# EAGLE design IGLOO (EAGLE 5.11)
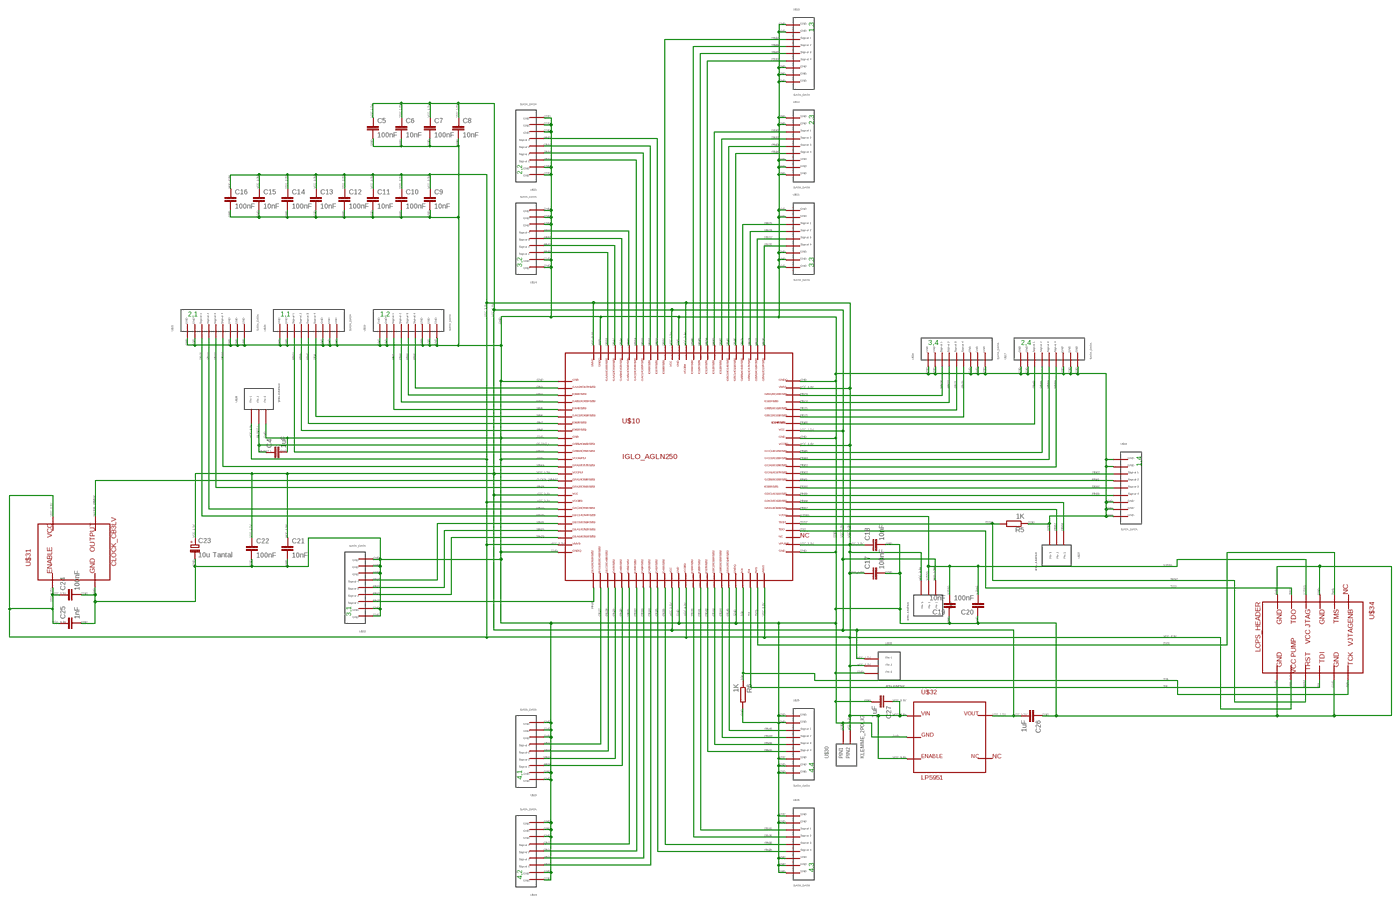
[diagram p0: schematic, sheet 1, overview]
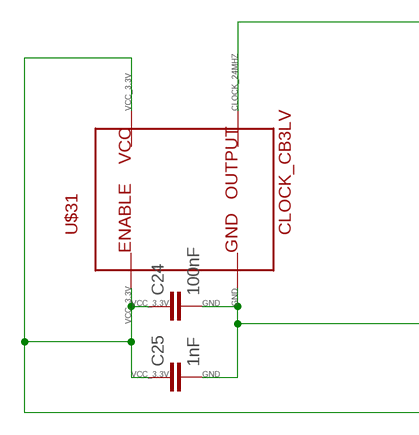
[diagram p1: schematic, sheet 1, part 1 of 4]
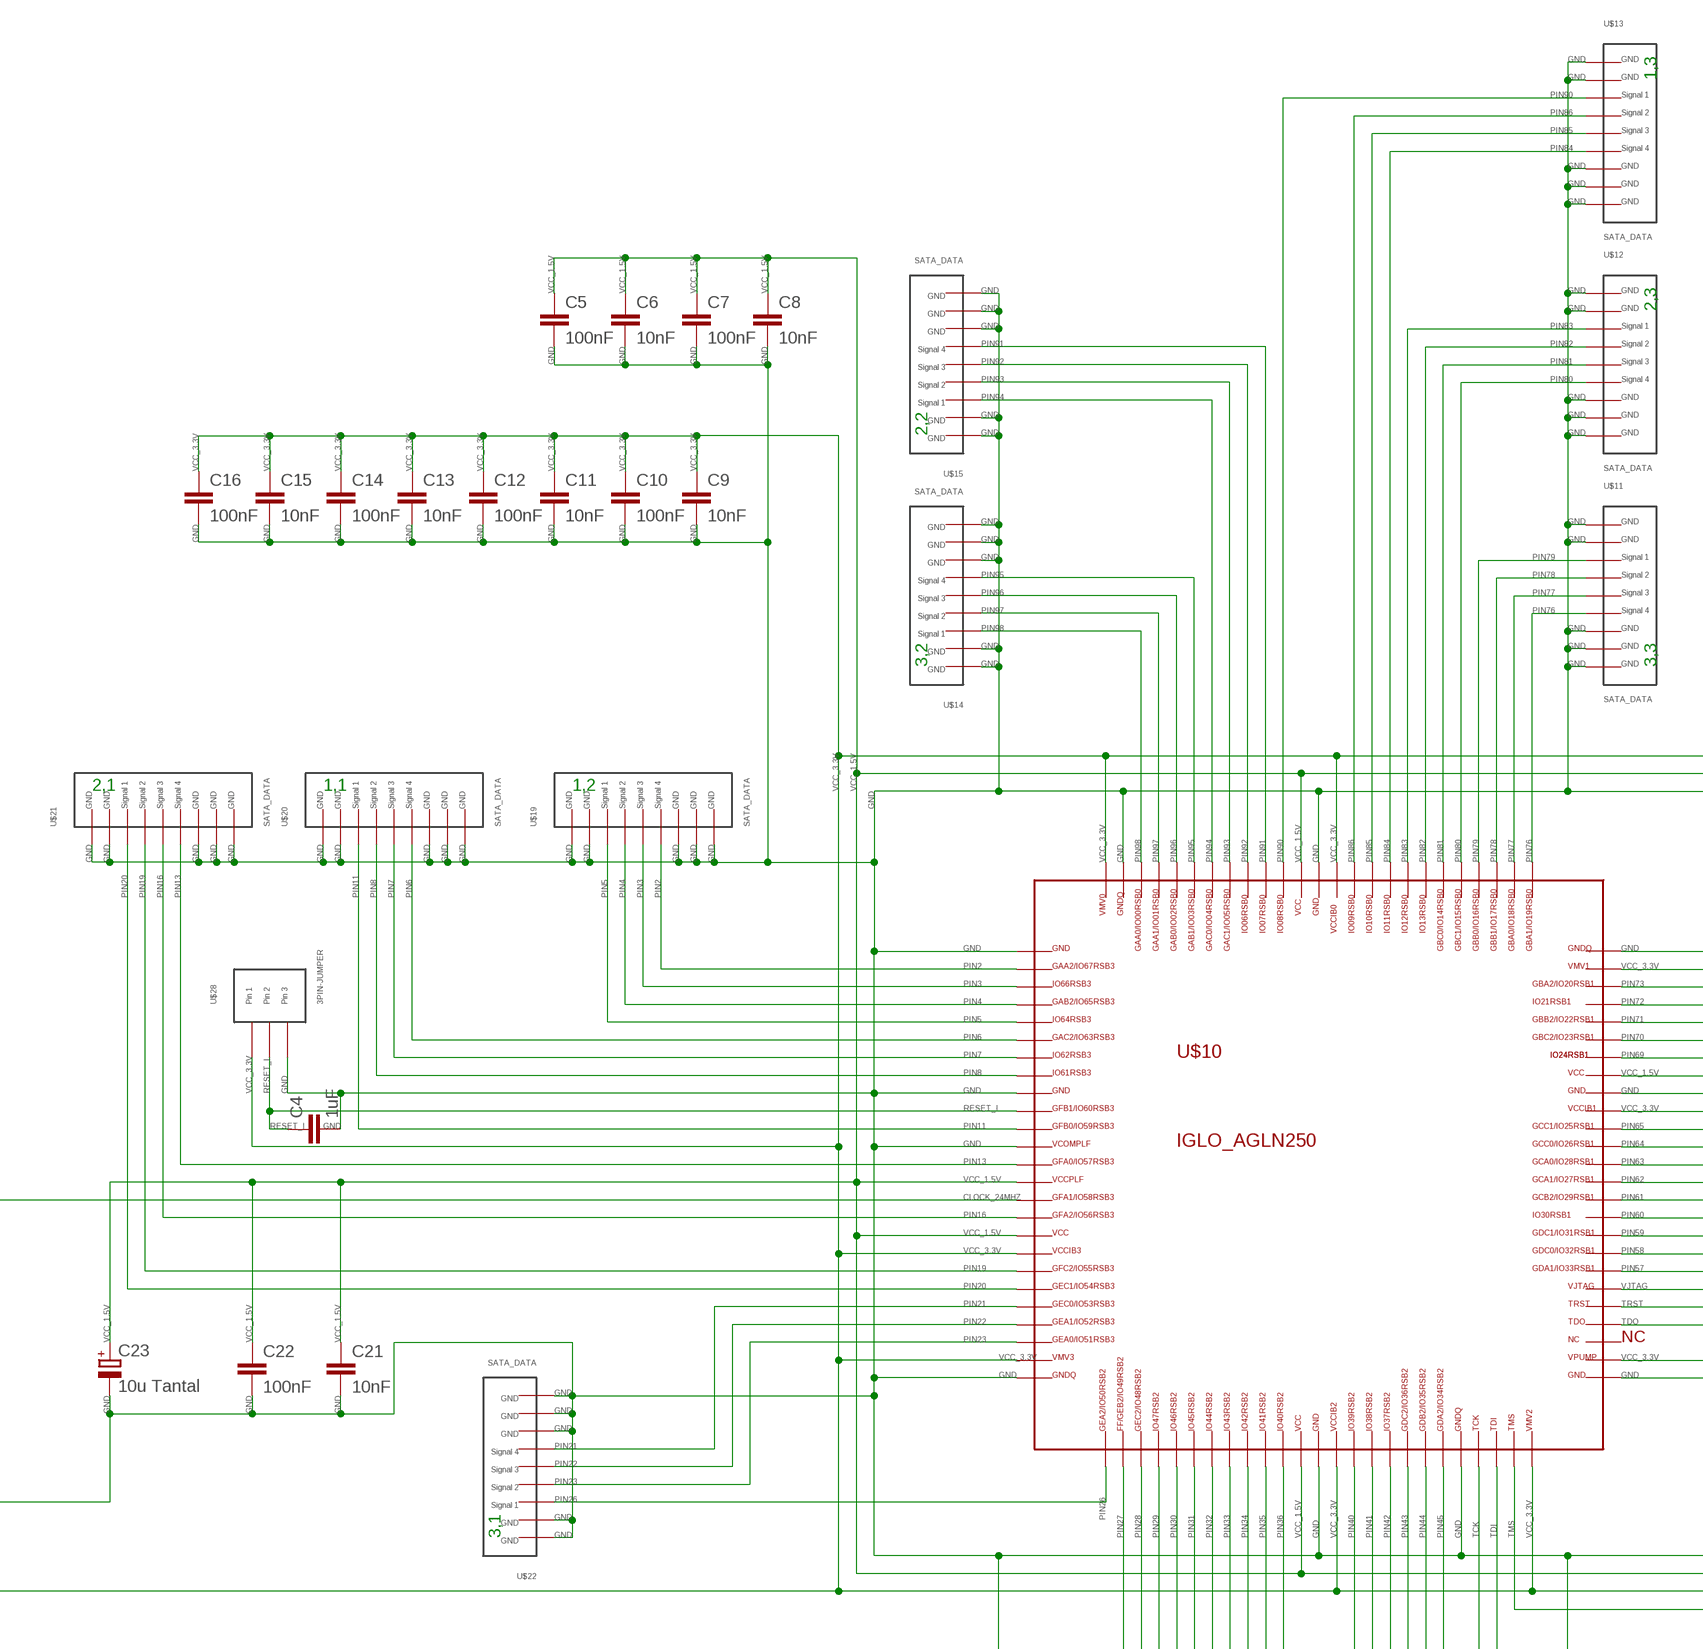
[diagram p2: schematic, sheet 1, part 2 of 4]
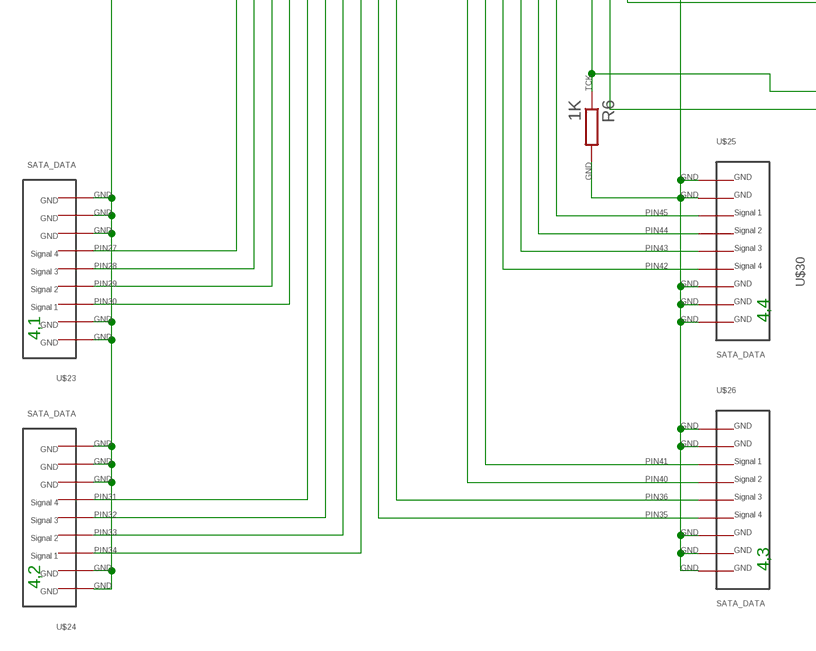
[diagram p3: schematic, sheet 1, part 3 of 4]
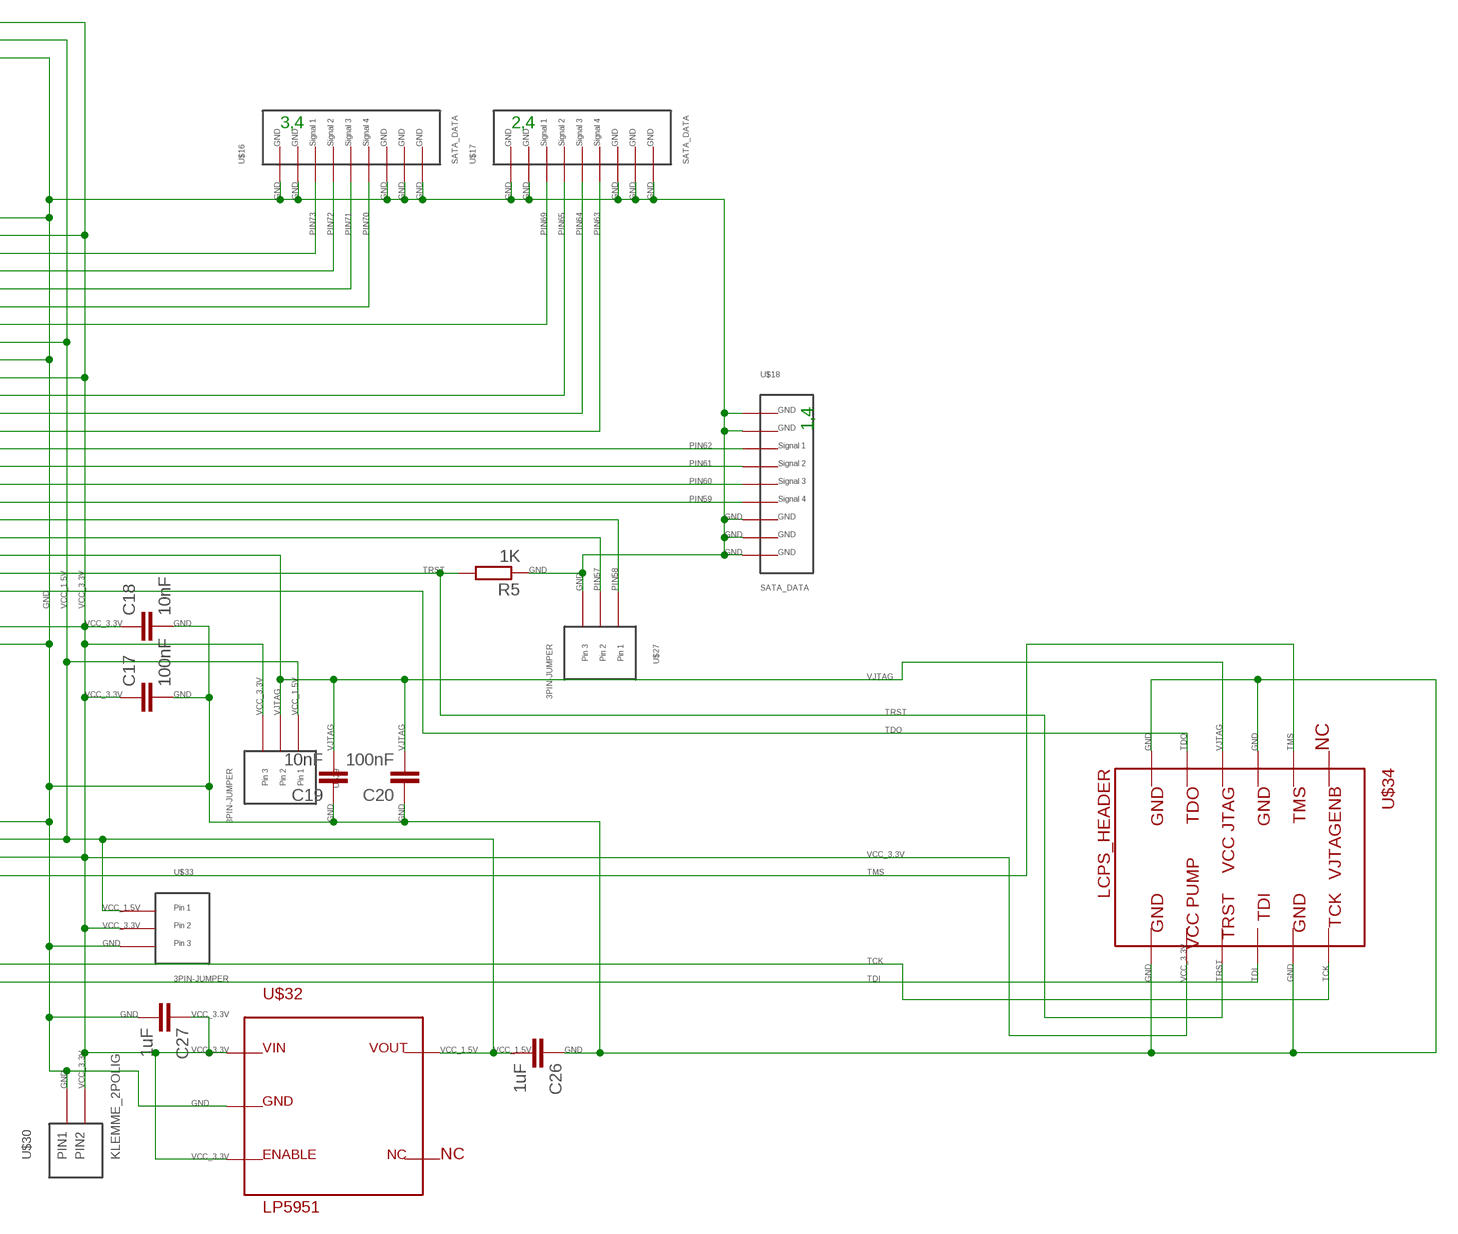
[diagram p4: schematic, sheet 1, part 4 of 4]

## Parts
C4  1uF  C-EUC0805  [C0805]
C5  100nF  C-EUC0805  [C0805]
C6  10nF  C-EUC0805  [C0805]
C7  100nF  C-EUC0805  [C0805]
C8  10nF  C-EUC0805  [C0805]
C9  10nF  C-EUC0805  [C0805]
C10  100nF  C-EUC0805  [C0805]
C11  10nF  C-EUC0805  [C0805]
C12  100nF  C-EUC0805  [C0805]
C13  10nF  C-EUC0805  [C0805]
C14  100nF  C-EUC0805  [C0805]
C15  10nF  C-EUC0805  [C0805]
C16  100nF  C-EUC0805  [C0805]
C17  100nF  C-EUC0805  [C0805]
C18  10nF  C-EUC0805  [C0805]
C19  10nF  C-EUC0805  [C0805]
C20  100nF  C-EUC0805  [C0805]
C21  10nF  C-EUC0805  [C0805]
C22  100nF  C-EUC0805  [C0805]
C23  10u Tantal  CPOL-EUSMCA  [SMC_A]
C24  100nF  C-EUC0805  [C0805]
C25  1nF  C-EUC0805  [C0805]
C26  1uF  C-EUC0805  [C0805]
C27  1uF  C-EUC0805  [C0805]
R5  1K  R-EU_R0805  [R0805]
R6  1K  R-EU_R0805  [R0805]
U$10  IGLO_AGLN250  [VQ100]
U$11  SATA_DATA  [MOLEX_SATA_PLUG]
U$12  SATA_DATA  [MOLEX_SATA_PLUG]
U$13  SATA_DATA  [MOLEX_SATA_PLUG]
U$14  SATA_DATA  [MOLEX_SATA_PLUG]
U$15  SATA_DATA  [MOLEX_SATA_PLUG]
U$16  SATA_DATA  [MOLEX_SATA_PLUG]
U$17  SATA_DATA  [MOLEX_SATA_PLUG]
U$18  SATA_DATA  [MOLEX_SATA_PLUG]
U$19  SATA_DATA  [MOLEX_SATA_PLUG]
U$20  SATA_DATA  [MOLEX_SATA_PLUG]
U$21  SATA_DATA  [MOLEX_SATA_PLUG]
U$22  SATA_DATA  [MOLEX_SATA_PLUG]
U$23  SATA_DATA  [MOLEX_SATA_PLUG]
U$24  SATA_DATA  [MOLEX_SATA_PLUG]
U$25  SATA_DATA  [MOLEX_SATA_PLUG]
U$26  SATA_DATA  [MOLEX_SATA_PLUG]
U$27  3PIN-JUMPER  [3PIN_JUMPER]
U$28  3PIN-JUMPER  [3PIN_JUMPER]
U$29  3PIN-JUMPER  [3PIN_JUMPER]
U$30  KLEMME_2POLIG  [KLEMME_2POL_PACK]
U$31  CLOCK_CB3LV  [CLOCK_CB3LV]
U$32  LP5951  [DBV]
U$33  3PIN-JUMPER  [3PIN_JUMPER]
U$34  LCPS_HEADER  [LCPS_HEADER]

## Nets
CLOCK_24MHZ: U$10.P$15 U$31.P$3
GND: C4.2 C5.2 C6.2 C7.2 C8.2 C9.2 C10.2 C11.2 C12.2 C13.2 C14.2 C15.2 C16.2 C17.2 C18.2 C19.1 C20.1 C21.2 C22.2 C23.- C24.2 C25.2 C26.1 C27.2 R5.1 R6.2 U$10.P$1 U$10.P$9 U$10.P$12 U$10.P$25 U$10.P$38 U$10.P$46 U$10.P$51 U$10.P$67 U$10.P$75 U$10.P$88 U$10.P$99 U$11.P$1 U$11.P$4 U$11.P$7 U$11.P$8 U$11.P$9 U$12.P$1 U$12.P$4 U$12.P$7 U$12.P$8 U$12.P$9 U$13.P$1 U$13.P$4 U$13.P$7 U$13.P$8 U$13.P$9 U$14.P$1 U$14.P$4 U$14.P$7 U$14.P$8 U$14.P$9 U$15.P$1 U$15.P$4 U$15.P$7 U$15.P$8 U$15.P$9 U$16.P$1 U$16.P$4 U$16.P$7 U$16.P$8 U$16.P$9 U$17.P$1 U$17.P$4 U$17.P$7 U$17.P$8 U$17.P$9 U$18.P$1 U$18.P$4 U$18.P$7 U$18.P$8 U$18.P$9 U$19.P$1 U$19.P$4 U$19.P$7 U$19.P$8 U$19.P$9 U$20.P$1 U$20.P$4 U$20.P$7 U$20.P$8 U$20.P$9 U$21.P$1 U$21.P$4 U$21.P$7 U$21.P$8 U$21.P$9 U$22.P$1 U$22.P$4 U$22.P$7 U$22.P$8 U$22.P$9 U$23.P$1 U$23.P$4 U$23.P$7 U$23.P$8 U$23.P$9 U$24.P$1 U$24.P$4 U$24.P$7 U$24.P$8 U$24.P$9 U$25.P$1 U$25.P$4 U$25.P$7 U$25.P$8 U$25.P$9 U$26.P$1 U$26.P$4 U$26.P$7 U$26.P$8 U$26.P$9 U$27.P$3 U$28.P$3 U$30.P$1 U$31.P$2 U$32.P$2 U$33.P$3 U$34.P$4 U$34.P$5 U$34.P$11 U$34.P$12
PIN2: U$10.P$2 U$19.P$6
PIN3: U$10.P$3 U$19.P$5
PIN4: U$10.P$4 U$19.P$3
PIN5: U$10.P$5 U$19.P$2
PIN6: U$10.P$6 U$20.P$6
PIN7: U$10.P$7 U$20.P$5
PIN8: U$10.P$8 U$20.P$3
PIN11: U$10.P$11 U$20.P$2
PIN13: U$10.P$13 U$21.P$6
PIN16: U$10.P$16 U$21.P$5
PIN19: U$10.P$19 U$21.P$3
PIN20: U$10.P$20 U$21.P$2
PIN21: U$10.P$21 U$22.P$6
PIN22: U$10.P$22 U$22.P$5
PIN23: U$10.P$23 U$22.P$3
PIN26: U$10.P$26 U$22.P$2
PIN27: U$10.P$27 U$23.P$6
PIN28: U$10.P$28 U$23.P$5
PIN29: U$10.P$29 U$23.P$3
PIN30: U$10.P$30 U$23.P$2
PIN31: U$10.P$31 U$24.P$6
PIN32: U$10.P$32 U$24.P$5
PIN33: U$10.P$33 U$24.P$3
PIN34: U$10.P$34 U$24.P$2
PIN35: U$10.P$35 U$26.P$6
PIN36: U$10.P$36 U$26.P$5
PIN40: U$10.P$40 U$26.P$3
PIN41: U$10.P$41 U$26.P$2
PIN42: U$10.P$42 U$25.P$6
PIN43: U$10.P$43 U$25.P$5
PIN44: U$10.P$44 U$25.P$3
PIN45: U$10.P$45 U$25.P$2
PIN57: U$10.P$57 U$27.P$2
PIN58: U$10.P$58 U$27.P$1
PIN59: U$10.P$59 U$18.P$6
PIN60: U$10.P$60 U$18.P$5
PIN61: U$10.P$61 U$18.P$3
PIN62: U$10.P$62 U$18.P$2
PIN63: U$10.P$63 U$17.P$6
PIN64: U$10.P$64 U$17.P$5
PIN65: U$10.P$65 U$17.P$3
PIN69: U$10.P$69 U$17.P$2
PIN70: U$10.P$70 U$16.P$6
PIN71: U$10.P$71 U$16.P$5
PIN72: U$10.P$72 U$16.P$3
PIN73: U$10.P$73 U$16.P$2
PIN76: U$10.P$76 U$11.P$6
PIN77: U$10.P$77 U$11.P$5
PIN78: U$10.P$78 U$11.P$3
PIN79: U$10.P$79 U$11.P$2
PIN80: U$10.P$80 U$12.P$6
PIN81: U$10.P$81 U$12.P$5
PIN82: U$10.P$82 U$12.P$3
PIN83: U$10.P$83 U$12.P$2
PIN84: U$10.P$84 U$13.P$6
PIN85: U$10.P$85 U$13.P$5
PIN86: U$10.P$86 U$13.P$3
PIN90: U$10.P$90 U$13.P$2
PIN91: U$10.P$91 U$15.P$6
PIN92: U$10.P$92 U$15.P$5
PIN93: U$10.P$93 U$15.P$3
PIN94: U$10.P$94 U$15.P$2
PIN95: U$10.P$95 U$14.P$6
PIN96: U$10.P$96 U$14.P$5
PIN97: U$10.P$97 U$14.P$3
PIN98: U$10.P$98 U$14.P$2
RESET_I: C4.1 U$10.P$10 U$28.P$2
TCK: R6.1 U$10.P$47 U$34.P$2
TDI: U$10.P$48 U$34.P$6
TDO: U$10.P$54 U$34.P$9
TMS: U$10.P$49 U$34.P$3
TRST: R5.2 U$10.P$55 U$34.P$8
VCC_1.5V: C5.1 C6.1 C7.1 C8.1 C21.1 C22.1 C23.+ C26.2 U$10.P$14 U$10.P$17 U$10.P$37 U$10.P$68 U$10.P$89 U$29.P$1 U$32.P$5 U$33.P$1
VCC_3.3V: C9.1 C10.1 C11.1 C12.1 C13.1 C14.1 C15.1 C16.1 C17.1 C18.1 C24.1 C25.1 C27.1 U$10.P$18 U$10.P$24 U$10.P$39 U$10.P$50 U$10.P$52 U$10.P$66 U$10.P$74 U$10.P$87 U$10.P$100 U$28.P$1 U$29.P$3 U$30.P$2 U$31.P$1 U$31.P$4 U$32.P$1 U$32.P$3 U$33.P$2 U$34.P$10
VJTAG: C19.2 C20.2 U$10.P$56 U$29.P$2 U$34.P$7
Unconnected: U$10.P$53 U$32.P$4 U$34.P$1

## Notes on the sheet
- 1,3
- 2,3
- 2,2
- 3,2 | 3,3
- 2,1 | 1,1 | 1,2
- 3,4 | 2,4
- 1,4
- NC
- NC
- 3,1
- NC
- 4,4
- 4,1
- 4,3
- 4,2

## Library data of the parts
C4-C22 C24-C27 = rcl:C-EU: CAPACITOR, European symbol
C23 = rcl:CPOL-EU: POLARIZED CAPACITOR, European symbol
R5 R6 = rcl:R-EU_: RESISTOR, European symbol
U$10 = IGLOO_NANO:IGLO_AGLN250
U$11-U$26 = mylibs:SATA_DATA
U$27-U$29 U$33 = mylibs:3PIN-JUMPER
U$30 = mypowerlib:KLEMME_2POLIG
U$31 = CLOCK_CB3LV:CLOCK_CB3LV
U$32 = LP5951:LP5951
U$34 = LCPS_Header:LCPS_HEADER

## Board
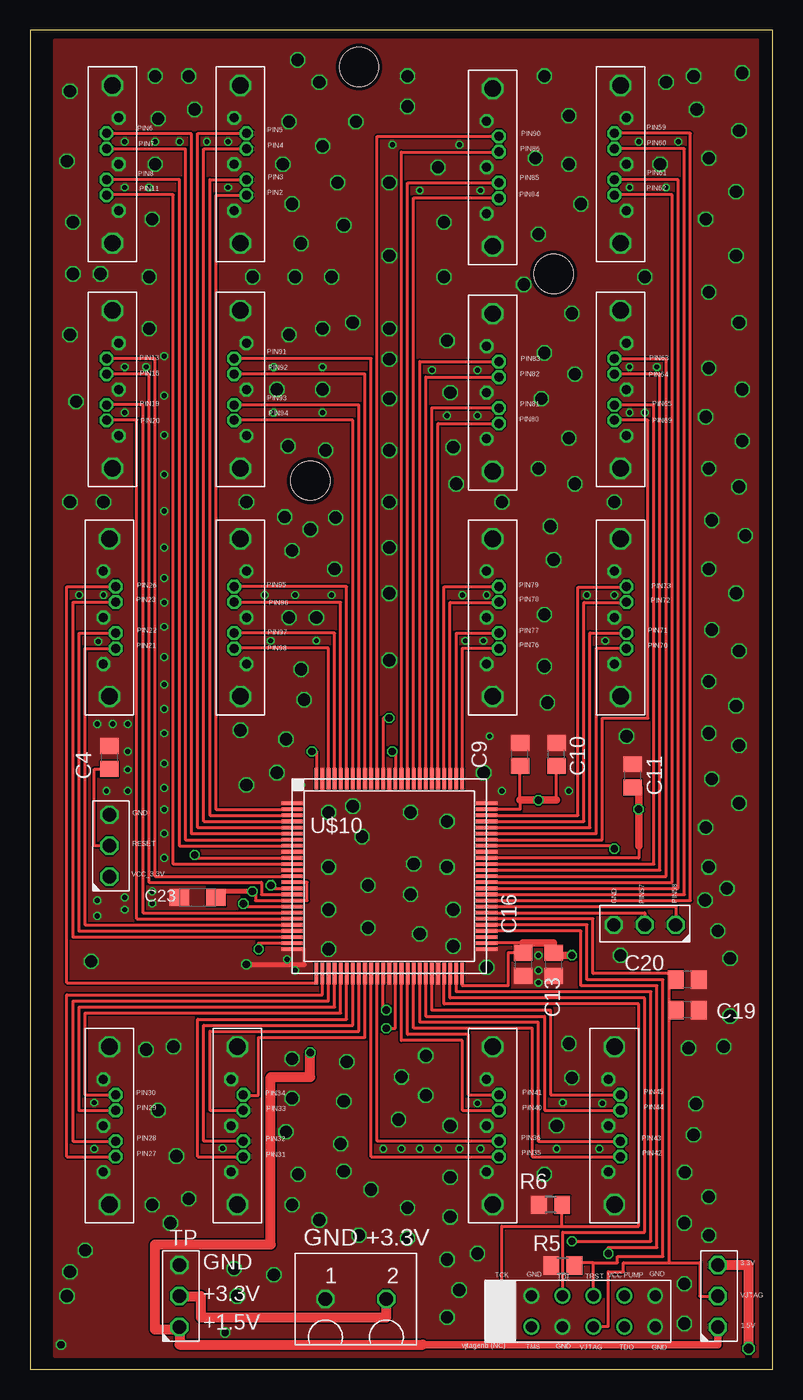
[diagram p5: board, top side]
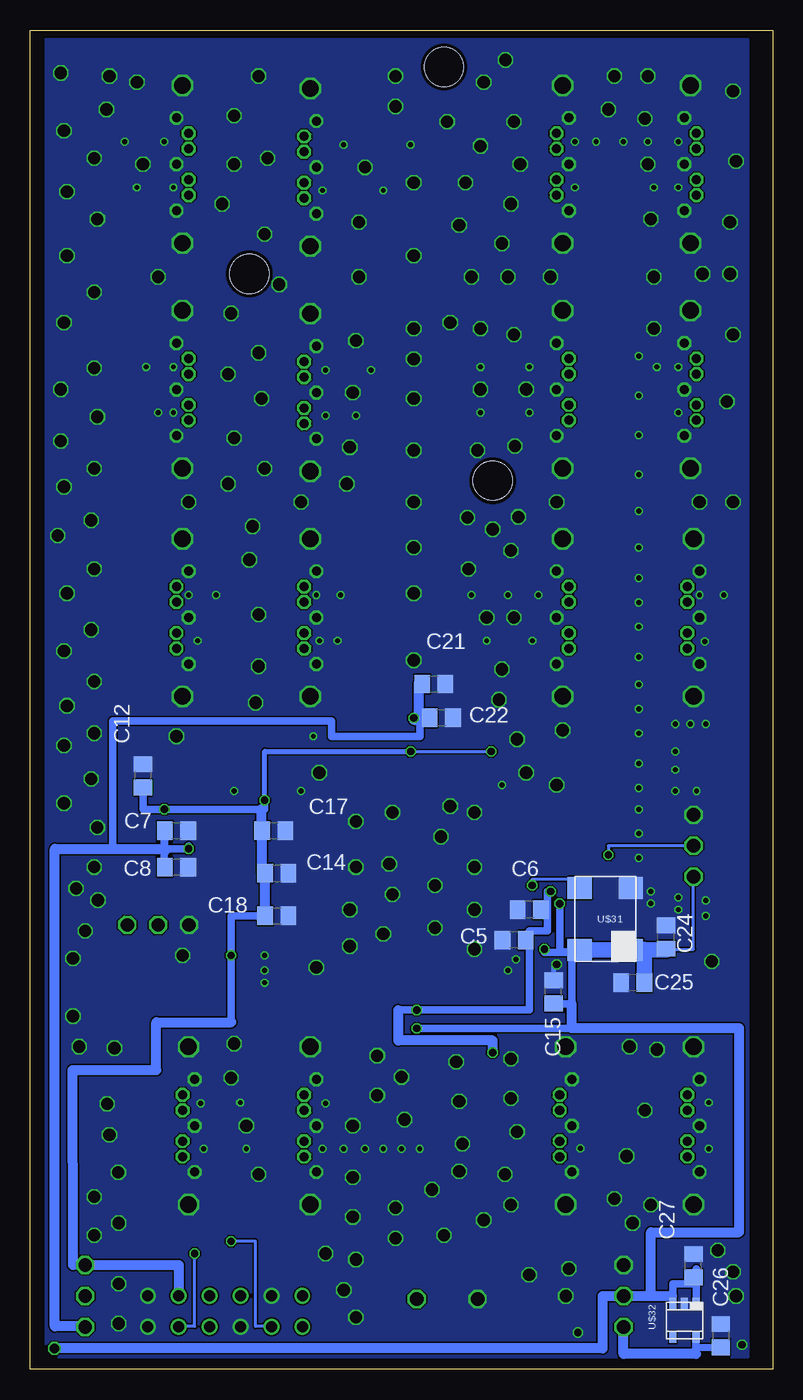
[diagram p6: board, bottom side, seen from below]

Size 61 x 110 mm. Coordinates in mm from the lower left corner, seen from the top.
Outline: 0,0 61,0 61,110 0,110 0,0
Copper layers (1*16): Top 0.035mm / dielectric 1.5mm / Bottom 0.035mm
Design rules "PCB-POOL HighSpec": minimum track width 0.125mm, minimum drill 0.2mm, track to track 0.125mm, track to pad 0.125mm, pad to pad 0.125mm, via to via 0.125mm, smd to smd 0.125mm, copper to edge 0.3mm, drill to drill 0.2mm, minimum pad ring 0.2mm, minimum via ring 0.125mm, stop-mask expansion 0.075mm, vias tented up to drill 0mil, thermal gap 0.2mm
Holes 3.2 mm at 27,107 43,90 23,73

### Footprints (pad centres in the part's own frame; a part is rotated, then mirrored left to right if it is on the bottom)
C0805 = smd 1.3 x 1.5: 1 -0.95,0; 2 0.95,0
SMC_A = smd 1.6 x 1.4: + -1.5,0; - 1.5,0
R0805 = smd 1.3 x 1.5: 1 -0.95,0; 2 0.95,0
VQ100 = smd 1.75 x 0.3: P$1 -8,6; P$2 -8,5.5; P$3 -8,5; P$4 -8,4.5; P$5 -8,4; P$6 -8,3.5; P$7 -8,3; P$8 -8,2.5; P$9 -8,2; P$10 -8,1.5; P$11 -8,1; P$12 -8,0.5; P$13 -8,0; P$14 -8,-0.5; P$15 -8,-1; P$16 -8,-1.5; P$17 -8,-2; P$18 -8,-2.5; P$19 -8,-3; P$20 -8,-3.5; P$21 -8,-4; P$22 -8,-4.5; P$23 -8,-5; P$24 -8,-5.5; P$25 -8,-6; P$51 8,-6; P$52 8,-5.5; P$53 8,-5; P$54 8,-4.5; P$55 8,-4; P$56 8,-3.5; P$57 8,-3; P$58 8,-2.5; P$59 8,-2; P$60 8,-1.5; P$61 8,-1; P$62 8,-0.5; P$63 8,0; P$64 8,0.5; P$65 8,1; P$66 8,1.5; P$67 8,2; P$68 8,2.5; P$69 8,3; P$70 8,3.5; P$71 8,4; P$72 8,4.5; P$73 8,5; P$74 8,5.5; P$75 8,6 | smd 0.3 x 1.75: P$26 -6,-8; P$27 -5.5,-8; P$28 -5,-8; P$29 -4.5,-8; P$30 -4,-8; P$31 -3.5,-8; P$32 -3,-8; P$33 -2.5,-8; P$34 -2,-8; P$35 -1.5,-8; P$36 -1,-8; P$37 -0.5,-8; P$38 0,-8; P$39 0.5,-8; P$40 1,-8; P$41 1.5,-8; P$42 2,-8; P$43 2.5,-8; P$44 3,-8; P$45 3.5,-8; P$46 4,-8; P$47 4.5,-8; P$48 5,-8; P$49 5.5,-8; P$50 6,-8; P$76 6,8; P$77 5.5,8; P$78 5,8; P$79 4.5,8; P$80 4,8; P$81 3.5,8; P$82 3,8; P$83 2.5,8; P$84 2,8; P$85 1.5,8; P$86 1,8; P$87 0.5,8; P$88 0,8; P$89 -0.5,8; P$90 -1,8; P$91 -1.5,8; P$92 -2,8; P$93 -2.5,8; P$94 -3,8; P$95 -3.5,8; P$96 -4,8; P$97 -4.5,8; P$98 -5,8; P$99 -5.5,8; P$100 -6,8
MOLEX_SATA_PLUG = drill 0.74 pad 1.016 octagon: P$1 -3.81,-0.5; P$2 -2.54,0.5; P$3 -1.27,0.5; P$4 0,-0.5; P$5 1.27,0.5; P$6 2.54,0.5; P$7 3.81,-0.5 | drill 1.35 octagon: P$8 -6.48,0; P$9 6.48,0
3PIN_JUMPER = drill 1.1 octagon: P$1 -2.54,0; P$2 0,0; P$3 2.54,0
KLEMME_2POL_PACK = drill 1.1 octagon: P$1 -2.5,0; P$2 2.5,0
CLOCK_CB3LV = smd 1.8 x 2: P$1 -2.54,-2.1; P$2 2.54,-2.1; P$3 2.54,2.1; P$4 -2.54,2.1
DBV = smd 0.6 x 0.9: P$1 -0.95,-1.4; P$2 0,-1.4; P$3 0.95,-1.4; P$4 0.95,1.4; P$5 -0.95,1.4
LCPS_HEADER = drill 0.9 round: P$1 -6.35,-1.27; P$2 -6.35,1.27; P$3 -3.81,-1.27; P$4 -3.81,1.27; P$5 -1.27,-1.27; P$6 -1.27,1.27; P$7 1.27,-1.27; P$8 1.27,1.27; P$9 3.81,-1.27; P$10 3.81,1.27; P$11 6.35,-1.27; P$12 6.35,1.27

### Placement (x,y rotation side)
C4  6.5,50.25 90 top
C5  21.25,35.25 180 bottom
C6  20,37.75 180 bottom
C7  49,44.25 0 bottom
C8  49,41.25 0 bottom
C9  40.25,50.5 90 top
C10  43.25,50.5 90 top
C11  49.5,48.75 90 top
C12  51.75,48.75 90 bottom
C13  43,33.25 270 top
C14  40.75,40.75 0 bottom
C15  18,31 90 bottom
C16  40.5,33.25 270 top
C17  41,44.25 0 bottom
C18  40.75,37.25 0 bottom
C19  54,29.5 180 top
C20  54,32 180 top
C21  27.85,56.3 0 bottom
C22  27.23,53.53 0 bottom
C23  13.75,38.75 180 top
C24  8.75,35.5 90 bottom
C25  11.5,31.75 180 bottom
C26  4.25,2.75 270 bottom
C27  6.5,8.5 90 bottom
R5  43.75,8.5 0 top
R6  42.75,13.5 180 top
U$10  29.5,40.5 0 top
U$11  38,61.75 270 top
U$12  38,80.25 270 top
U$13  38,98.75 270 top
U$14  17.25,61.75 90 top
U$15  17.25,80.5 90 top
U$16  48.5,61.75 270 top
U$17  48.5,80.5 90 top
U$18  48.5,99 90 top
U$19  17.25,99 270 top
U$20  6.75,99 90 top
U$21  6.75,80.5 90 top
U$22  6.5,61.75 270 top
U$23  6.5,20 270 top
U$24  17,20 270 top
U$25  48,20 270 top
U$26  38,20 270 top
U$27  50.5,36.5 180 top
U$28  6.5,43 90 top
U$29  56.5,6 90 top
U$30  26.75,5.75 0 top
U$31  13.75,37 90 bottom
U$32  7.25,4 180 bottom
U$33  12.25,6 90 top
U$34  45,4.75 0 top

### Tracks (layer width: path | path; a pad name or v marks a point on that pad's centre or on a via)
CLOCK_24MHZ  (via drill 0.6)
  Top 0.25: U$10.P$15 19.75,39.5 v19.75,39.75
  Bottom 0.25: v19.75,39.75 19.75,40.25 16.25,40.25 16.35,39.75 U$31.P$3
GND  (via drill 0.4, 0.6, 1)
  Top 0.25: 22.5,33.25 22.5,34.5 U$10.P$25
  Top 0.406: v17.75,33.25 22.5,33.25
  Bottom 0.406: C15.2 18,33.25 v17.75,33.25
  other vias: 24.5,45.75 27.25,43.75 24.5,41.25 27.75,39.75 24.5,37.75 27.75,36.25 24.5,34.5 31.25,45.75 34.25,45 31.5,41.5 34.25,41.25 31.25,39 34.75,37.75 32,35.75 34.75,34.75 26.5,46.25 17.75,48 17.25,52.5 22.25,57.5 21,51.75 22.5,55 20.25,49 24.25,75.5 21.18,75.85 17.75,71.25 20.9,70.03 25.07,69.97 21.5,67.25 25,65.75 23,69 6,71.25 9.75,89.75 10,94.5 9.75,85.5 18.25,89.75 21.25,85 22.25,92.5 21.75,89.75 24,85.5 24.75,89.75 26.5,86 25.75,94 21.5,95.75 25.25,97.5 20.75,99 24,100.5 21.25,102.5 23.75,105.75 26.75,102.5 31,106.25 33.5,98.75 31,103.75 21.95,107.57 10.25,106.25 10.5,102.75 13,106.25 13.5,103.5 10.25,99 3.25,105 3,99.25 3.5,94.25 3.5,90 5.75,90 42.25,106.25 44.25,103 41.5,99.5 45.25,95.75 41.75,93.25 44.25,99 34,94.25 34,89.75 40.55,89.12 50.5,89.75 52.25,105.75 51.75,99 20.25,80.5 24,80.5 29.5,83 34.5,80.25 34.75,75.75 35,72.75 42.25,83.5 44.5,86.75 44.25,76.5 44.75,81.75 42,79.75 41.75,74 44.75,72.75 34.25,84.5 29.5,97.5 29.5,91.5 29.5,85.5 29.5,79.75 29.5,75.5 29.5,71.25 29.5,67.5 29.5,63.75 29.5,58.25 23.5,61.75 21.25,61.75 3.25,85 3.75,79.5 3.25,71.25 42.75,69.25 38.75,71.25 48,71.25 43,66.5 42.25,62 42.25,57.75 42.5,54.75 9.5,26.25 11.75,26.5 10.5,21.25 12,17.5 10,13.5 13,14 25.5,18.5 22,16 28,14.75 23.75,12.25 27,11 16,3 17,6 20,7.75 16.75,8.25 11.5,12 3,6 4.5,9.75 34.5,15.75 31,13.25 25.75,16.25 31,10.75 34.5,12.5 34.25,9 34.25,4.25 36.75,9.5 35.25,6.5 53.75,7 53.75,3.75 53.75,12 44.5,23.92 55.75,11 53.77,16.17 43.25,20 30.5,24 25.75,22 54.5,19.25 55.75,14.15 54.1,26.38 54.7,21.8 57,26.5 57.5,29 57.5,33.75 48.5,34 56.5,36 57.25,39.5 55.75,41.25 55.45,38.53 55.5,44.5 58.25,46.5 56,48.5 58.25,51.25 55.75,52.25 49,52 58,54.5 55.75,56.5 58.25,59 56,60.75 58,63.75 55.75,65.75 58.75,68.5 56,69.75 58.25,72.5 55.75,74 58.5,76.25 55.5,78.25 58.5,80.5 55.75,82.25 58.25,86 55.75,88.5 58,91.5 55.5,94.5 58,96.75 55.75,99.5 58.25,101.75 54.75,103.5 58.5,106.5 54.5,106.25 21.5,25.5 26,25.25 21.5,22.25 30.25,20.5 21,19.5 42.25,16 44.25,26.75 5,33.5 21.5,13.5 37.5,33 41.75,31.75 41.75,32.75 41.75,34 10,38.25 11,42 11,44 11,46 11,47.75 11,49.75 11,52.25 5.5,53 6.75,53 8,53 8,50.75 8,49.25 8,47.5 6.25,47.5 11,54.25 11,56.25 11,58.5 11,61 11,63 11,65 11,67.5 11,70.5 11,73.5 11,76.75 11,80 11,83.25 10,39.25 37.25,49 37.75,52 38.75,47.5 44.25,47.5 21.75,32.75 22.25,48 5.5,38.5 5.5,37.25 7.75,38.75 7.75,37.75 32.5,25.75 34.5,20 3.25,8 2.5,2 5.25,21.9 5.25,18.1 15.8,18.12 30.5,18.1 43.75,21.9 43.25,18.1 32,18.1 33.5,18.1 35.25,18.1 29,18.1 37,18.1 32.5,22.5 36.75,21.85 46.75,18.1 47,21.85 6,63.6 4,63.6 23.5,59.85 19.75,59.85 19.25,63.6 24.75,63.6 21.75,63.6 35.75,59.85 37.25,59.85 37.5,63.6 35.5,63.6 47.25,59.85 48,63.6 45.75,63.6 49.25,82.35 51.5,82.35 49.25,78.6 50.5,78.6 53.25,100.85 50,100.85 49.25,97.1 52.25,97.1 35.25,100.6 29.75,100.6 32,96.85 37,96.85 20,82.35 24,82.35 20,78.6 24,78.6 33,82.1 36.75,82.1 34.25,78.35 36.75,78.35 7.75,82.35 9.5,82.35 7.75,78.6 7.75,100.85 10.25,100.85 12.25,100.85 7.75,97.1 9.75,97.1 14.5,100.85 16.25,100.85 16.25,97.1 5.57,59.8 21.1,33.67
  pour Bottom (no thermals): 2,109.25 59.75,109.25 59.75,1 2,1
  pour Top (no thermals): 2,109.25 59.75,109.25 59.75,1 2,1
PIN2
  Top 0.25: U$10.P$2 15.25,46 15.25,96.46 U$19.P$6
PIN3
  Top 0.25: U$10.P$3 14.75,45.5 14.75,97.75 17.75,97.75 U$19.P$5
PIN4
  Top 0.25: U$10.P$4 14.25,45 14.25,100.27 U$19.P$3
PIN5
  Top 0.25: U$10.P$5 13.75,44.5 13.75,101.54 U$19.P$2
PIN6
  Top 0.25: U$10.P$6 13.25,44 13.25,101.5 6.25,101.5 U$20.P$6
PIN7
  Top 0.25: U$10.P$7 12.75,43.5 12.75,100.25 6.25,100.25 U$20.P$5
PIN8
  Top 0.25: U$10.P$8 12.25,43 12.25,97.75 6.25,97.75 U$20.P$3
PIN11
  Top 0.25: U$10.P$11 11.75,41.5 11.75,96.5 6.25,96.5 U$20.P$2
PIN13
  Top 0.25: U$10.P$13 10.25,40.5 10.25,83.04 U$21.P$6
PIN16
  Top 0.25: U$10.P$16 19,39 19,40 9.75,40 9.75,81.75 6.25,81.75 U$21.P$5
PIN19
  Top 0.25: U$10.P$19 9.25,37.5 9.25,79.25 6.25,79.25 U$21.P$3
PIN20
  Top 0.25: U$10.P$20 8.75,37 8.75,78 6.25,78 U$21.P$2
PIN21
  Top 0.25: U$10.P$21 4.5,36.5 4.5,59.21 U$22.P$6
PIN22
  Top 0.25: U$10.P$22 4,36 4,60.47 U$22.P$5
PIN23
  Top 0.25: U$10.P$23 3.5,35.5 3.5,63.02 U$22.P$3
PIN26
  Top 0.25: U$10.P$26 23.5,31.75 3,31.75 3,64.29 U$22.P$2
PIN27
  Top 0.25: U$10.P$27 24,30.75 3,30.75 3,17.46 U$23.P$6
PIN28
  Top 0.25: U$10.P$28 24.5,30.25 3.5,30.25 3.5,18.73 U$23.P$5
PIN29
  Top 0.25: U$10.P$29 25,29.75 4,29.75 4,21.25 7,21.25 U$23.P$3
PIN30
  Top 0.25: U$10.P$30 25.5,29.25 4.5,29.25 4.5,22.54 U$23.P$2
PIN31
  Top 0.25: U$10.P$31 26,28.75 13.75,28.75 13.75,17.46 U$24.P$6
PIN32
  Top 0.25: U$10.P$32 26.5,28.25 14.25,28.25 14.25,18.75 17.5,18.75 U$24.P$5
PIN33
  Top 0.25: U$10.P$33 27,27.75 14.75,27.75 14.75,21.27 U$24.P$3
PIN34
  Top 0.25: U$10.P$34 27.5,27.25 18.75,27.25 18.75,22.5 17.5,22.5 U$24.P$2
PIN35
  Top 0.25: U$10.P$35 28,17.46 U$26.P$6
PIN36
  Top 0.25: U$10.P$36 28.5,18.75 38.5,18.75 U$26.P$5
PIN40
  Top 0.25: U$10.P$40 30.5,27 35.5,27 35.5,21.27 U$26.P$3
PIN41
  Top 0.25: U$10.P$41 31,27.5 36,27.5 36,22.54 U$26.P$2
PIN42
  Top 0.25: U$10.P$42 31.5,28 41.25,28 41.25,17.46 U$25.P$6
PIN43
  Top 0.25: U$10.P$43 32,28.5 41.75,28.5 41.75,18.73 U$25.P$5
PIN44
  Top 0.25: U$10.P$44 32.5,29 42.25,29 42.25,21.27 U$25.P$3
PIN45
  Top 0.25: U$10.P$45 33,29.5 42.75,29.5 42.75,22.54 U$25.P$2
PIN57
  Top 0.25: U$10.P$57 50.5,37.5 U$27.P$2
PIN58
  Top 0.25: U$10.P$58 53.04,38 U$27.P$1
PIN59
  Top 0.25: U$10.P$59 54.25,38.5 54.25,101.54 U$18.P$6
PIN60
  Top 0.25: U$10.P$60 53.75,39 53.75,100.27 U$18.P$5
PIN61
  Top 0.25: U$10.P$61 53.25,39.5 53.25,97.73 U$18.P$3
PIN62
  Top 0.25: U$10.P$62 52.75,40 52.75,96.5 48,96.5 U$18.P$2
PIN63
  Top 0.25: U$10.P$63 52.25,40.5 52.25,83 48,83 U$17.P$6
PIN64
  Top 0.25: U$10.P$64 51.75,41 51.75,81.75 48,81.75 U$17.P$5
PIN65
  Top 0.25: U$10.P$65 51.25,41.5 51.25,79.23 U$17.P$3
PIN69
  Top 0.25: U$17.P$2 50.75,77.96 50.75,53.5 47,53.5 47,43.5 U$10.P$69
PIN70
  Top 0.25: U$10.P$70 46.5,44 46.5,59.25 49,59.25 U$16.P$6
PIN71
  Top 0.25: U$10.P$71 46,44.5 46,60.5 49,60.5 U$16.P$5
PIN72
  Top 0.25: U$10.P$72 45.5,45 45.5,63 49,63 U$16.P$3
PIN73
  Top 0.25: U$10.P$73 45,45.5 45,64.25 49,64.25 | 49,64.25 49.25,64.25 | 49,64.25 U$16.P$2
PIN76
  Top 0.25: U$10.P$76 35.5,59.25 38.5,59.25 U$11.P$6
PIN77
  Top 0.25: U$10.P$77 35,60.48 U$11.P$5
PIN78
  Top 0.25: U$10.P$78 34.5,63 38.5,63 U$11.P$3
PIN79
  Top 0.25: U$10.P$79 34,64.29 U$11.P$2
PIN80
  Top 0.25: U$10.P$80 33.5,77.71 U$12.P$6
PIN81
  Top 0.25: U$10.P$81 33,79 38.5,79 U$12.P$5
PIN82
  Top 0.25: U$10.P$82 32.5,81.52 U$12.P$3
PIN83
  Top 0.25: U$10.P$83 32,82.79 U$12.P$2
PIN84
  Top 0.25: U$10.P$84 31.5,96.25 38.5,96.25 U$13.P$6
PIN85
  Top 0.25: U$10.P$85 31,97.48 U$13.P$5
PIN86
  Top 0.25: U$10.P$86 30.5,100 38.5,100 U$13.P$3
PIN90
  Top 0.25: U$10.P$90 28.5,101.29 U$13.P$2
PIN91
  Top 0.25: U$10.P$91 28,83.04 U$15.P$6
PIN92
  Top 0.25: U$10.P$92 27.5,81.77 U$15.P$5
PIN93
  Top 0.25: U$10.P$93 27,79.23 U$15.P$3
PIN94
  Top 0.25: U$10.P$94 26.5,77.96 U$15.P$2
PIN95
  Top 0.25: U$10.P$95 26,64.29 U$14.P$6
PIN96
  Top 0.25: U$10.P$96 25.5,63 16.75,63 U$14.P$5
PIN97
  Top 0.25: U$10.P$97 25,60.48 U$14.P$3
PIN98
  Top 0.25: U$10.P$98 24.5,59.25 16.75,59.25 U$14.P$2
RESET_I  (via drill 0.6)
  Top 0.25: C4.1 5.25,49.3 5.25,43 U$28.P$2 | U$10.P$10 13.5,42 v13.5,42.25
  Bottom 0.25: v13.5,42.25 13.5,43 U$28.P$2
TCK
  Top 0.25: U$10.P$47 34,30 50,30 50,11.75 43.7,11.75 | 43.7,11.75 38.75,11.75 38.75,6 38.65,6 U$34.P$2 | 43.7,11.75 R6.1
TDI
  Top 0.25: U$10.P$48 34.5,30.5 50.5,30.5 50.5,11.25 43.75,11.25 43.75,6 43.73,6 U$34.P$6
TDO  (via drill 0.6)
  Top 0.25: U$10.P$54 45.25,36 45.25,31.5 51.5,31.5 51.5,10 47.5,10 v47.5,9.5
  Bottom 0.25: v47.5,9.5 47.5,3.5 48.81,3.5 U$34.P$9
TMS  (via drill 0.6)
  Top 0.25: U$10.P$49 35,31 51,31 51,10.5 v44.5,10.5
  Bottom 0.25: v44.5,10.5 42.5,10.5 42.5,3.5 41.19,3.5 U$34.P$3
TRST
  Top 0.25: U$10.P$55 45.75,36.5 45.75,32 52,32 52,9.25 48.25,9.25 48.25,8.75 46.27,8.75 | U$34.P$8 46.27,8.75 | R5.2 44.7,8.75 46.27,8.75
VCC_1.5V  (via drill 0.6)
  Top 0.25: U$10.P$14 22.75,40 22.75,38.5 U$10.P$17 18.5,38.5 18.5,39.25 v18.25,39.25 | v29.25,29.5 29,29.5 U$10.P$37 | U$10.P$68 48,43 v48,42.75 | U$10.P$89 29,53.5 v29.5,53.5
  Top 0.406: v18.25,39.25 15.25,39.25 C23.+
  Top 0.61: U$29.P$1 56.5,2 32.25,2
  Top 0.813: U$33.P$1 12.25,3.25 | 12.25,3.25 12.25,2 32.25,2 | v23,26 23,24 19.75,24 19.75,10.25 10.25,10.25 10.25,3.25 12.25,3.25
  Bottom 0.25: 28.23,53.5 C22.1 | 29,53.5 v29.5,53.5
  Bottom 0.61: v18.25,39.25 18.5,39.25 18.5,37.75 | 18.5,37.75 18.5,36 20,36 20,35.25 | 20,35.25 20,29.5 v29.25,29.5 30.75,29.5 | 18.5,37.75 C6.1 | 20,35.25 C5.1 | 6.3,1.75 6.3,1.25 | C26.2 6.3,1.75 | 6.3,1.75 U$32.P$5 | C8.1 50,41.25 50,42.5 50,44.25 C7.1 49.95,42.75 v48,42.75 48,43 | v29.5,53.5 28.23,53.5 | 29,53.5 29,52 36.25,52 36.25,53.25 54.25,53.25 54.25,42.75
  Bottom 0.813: 6.3,1.25 12.25,1.25 U$33.P$1 12.25,3.5 | 30.75,29.5 30.75,27 23,27 v23,26 | U$29.P$1 56.5,3.5 59,3.5 59,42.75 54.25,42.75 50,42.75 50,42.5 | C21.1 29.08,56.35 29.08,53.35 29.48,53.35 29.48,53.5 v29.5,53.5
VCC_3.3V  (via drill 0.6, 0.6 pad 0.61, 0.8)
  Top 0.25: U$10.P$18 17.5,38 v17.5,38.25 | U$10.P$24 18.75,35 v18.75,34.5 | U$10.P$39 30,28 v29.25,28 | U$10.P$74 40.25,46 40.25,46.75 C9.1 | 43.25,46.75 C10.1 | U$10.P$66 50,42 50,43 | U$10.P$52 40.5,35 C16.1 39.25,34.2 39.25,31.5 35.5,31.5 U$10.P$50 | C13.1 43,35 | U$10.P$87 30,50.75 v29.75,50.75 | U$10.P$100 23.5,50.75 v23.12,50.75
  Top 0.61: 50,43 v50,46 50,47.8 C11.1 | 43.25,46.75 v41.75,46.75 40.25,46.75 | 43,35 40.5,35 | v44.5,34 43.05,34 43,34
  Top 0.813: U$33.P$2 14,6 14,4.25 29.25,4.25 U$30.P$2 | U$29.P$3 59.03,8.54 v59.03,1.7 | C13.1 43.05,34.2 43.05,34
  Bottom 0.25: 16.5,34.46 16.25,34.46 | 16.5,34.46 17.5,34.46 | 16.5,34.25 16.5,34.46 | U$28.P$1 6.5,34.5 8.75,34.5 | v29.75,50.75 v23.12,50.75 | 12,34.5 12,34.42 11.73,34.42 11.73,34.46 11.88,34.46
  Bottom 0.406: 8.2,5.5 U$32.P$3 8.2,6 8.25,6 | v29.75,50.75 41.75,50.75 v41.75,46.75
  Bottom 0.61: 17.5,34.46 v17.5,38.25 | v18.75,34.5 18.75,34.25 16.5,34.25 16.5,30 18,30 C15.1 | 16.5,28 v29.25,28 | U$32.P$1 6.25,5.4 | 6.25,7 6.25,8.25 C27.1 | C12.1 51.75,46 v50,46 42,46 41.75,46 v41.75,46.75 | 44.5,28.5 v44.5,34 44.5,37.25 C18.1 | U$32.P$3 8.2,7 6.25,7 | 6.25,5.4 6.25,7 | 6.25,5.4 6.25,5.25
  Bottom 0.813: C18.1 C14.1 41.95,40.75 C17.1 42,44.25 42,46 | 10,6 10,11.25 2.75,11.25 2.75,28 16.5,28 16.5,30 | 10,6 U$33.P$2 13.98,6 13.98,1.7 v59.03,1.7 | 8.25,6 10,6 | U$34.P$10 48.81,8.55 56.52,8.55 | 56.52,8.55 56.52,8.48 56.5,8.48 U$29.P$3 | 44.5,28.5 50.65,28.5 50.65,24.58 57.52,24.58 57.5,9.25 57.5,8.55 56.52,8.55
  Bottom 1.27: 16.25,34.46 U$31.P$4 11.88,34.46 U$31.P$1 8.75,34.46 8.75,34.5 C24.1 | C25.1 10.55,34.5 12,34.5
VJTAG
  Top 0.25: U$10.P$56 46.25,37 46.25,32.5 52.5,32.5 | 52.5,8.75 52.5,29.5 | 52.5,29.5 52.5,32.5 | 52.5,8.75 48.75,8.75 48.75,8 47.5,8 47.5,3.5 46.27,3.5 U$34.P$7 | 52.5,8.75 55,8.75 55,6 U$29.P$2 | C20.2 53.05,32.5 52.5,32.5 | 52.5,29.5 C19.2

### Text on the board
tPlace: PIN6 | PIN5 | PIN59 | PIN90 | PIN60 | PIN7 | PIN4 | PIN86 | PIN8 | PIN3 | PIN85 | PIN61 | PIN11 | PIN62 | PIN2 | PIN84 | PIN13 | PIN91 | PIN83 | PIN63 | PIN16 | PIN92 | PIN82 | PIN64 | PIN93 | PIN19 | PIN81 | PIN65 | PIN20 | PIN94 | PIN80 | PIN69 | PIN26 | PIN95 | PIN79 | PIN73 | PIN23 | PIN96 | PIN78 | PIN72 | PIN22 | PIN97 | PIN77 | PIN71 | PIN21 | PIN98 | PIN76 | PIN70 | GND | RESET | VCC_3.3V | GND | PIN57 | PIN58 | PIN45 | PIN30 | PIN34 | PIN41 | PIN29 | PIN33 | PIN40 | PIN44 | PIN28 | PIN32 | PIN36 | PIN43 | PIN35 | PIN42 | PIN27 | PIN31 | TP | GND | +3.3V | GND | TCK | GND | VCC PUMP | GND | 3.3V | TDI | TRST | +3.3V | VJTAG | +1.5V | 1.5V | vjtagenb (NC) | TMS | GND | VJTAG | TDO | GND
